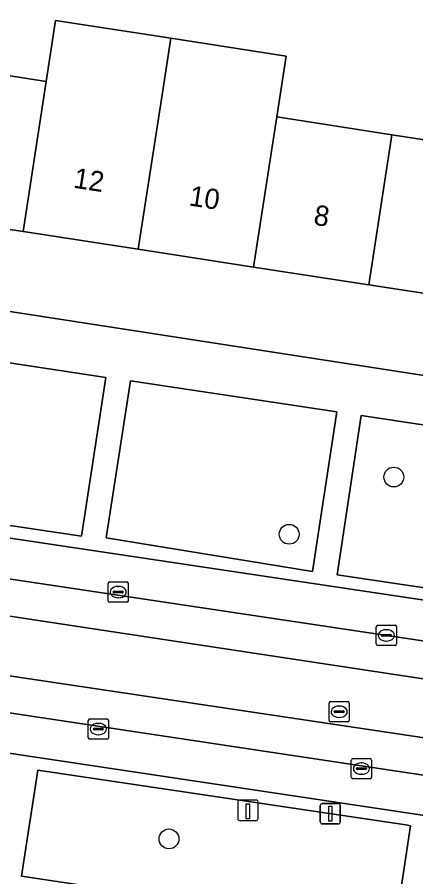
# Model space of a CAD drawing. Extents: x 163008 to 163854, y 382777 to 383982.
# Drawn here: x 163693.29 to 163712.99, y 383182.42 to 383224.9 of the extents above; entities that cross this region are included whole.
import ezdxf

# ---------------------------------------------------------------- set-up
doc = ezdxf.new("R2010")
doc.units = 0
for name, color, linetype in [('IMGEO_Boom', 7, 'Continuous'), ('IMGEO_Erf', 7, 'Continuous'), ('IMGEO_Groenvoorziening', 7, 'Continuous'), ('IMGEO_Kolk', 7, 'Continuous'), ('IMGEO_Laadpaal', 7, 'Continuous'), ('IMGEO_Lichtmast', 7, 'Continuous'), ('IMGEO_Pand', 7, 'Continuous'), ('IMGEO_Pand_nummerreeks', 7, 'Continuous'), ('IMGEO_Parkeervlak_open', 7, 'Continuous'), ('IMGEO_Rijbaan_lokaal_gesloten', 7, 'Continuous'), ('IMGEO_Rijbaan_lokaal_open', 7, 'Continuous'), ('IMGEO_Rioolput', 7, 'Continuous'), ('IMGEO_Voetpad_open', 7, 'Continuous')]:
    doc.layers.add(name, color=color, linetype=linetype)

msp = doc.modelspace()

# ---------------------------------------------------------------- linework, layer by layer
at = {"layer": 'IMGEO_Boom'}
for centre in [(163711.9, 383202.175), (163706.73, 383199.348), (163700.792, 383184.295)]:
    msp.add_circle(centre, 0.489, dxfattribs=at)
at = {"layer": 'IMGEO_Erf'}
for points in [[(163684.611, 383233.617), (163683.271, 383223.496), (163688.213, 383222.734), (163689.034, 383222.607), (163694.727, 383221.729), (163695.191, 383224.738), (163700.883, 383223.86), (163706.576, 383222.981), (163706.112, 383219.973), (163711.805, 383219.095), (163717.497, 383218.217), (163723.191, 383217.338), (163728.883, 383216.46), (163729.422, 383219.714), (163732.229, 383219.226), (163733.2, 383222.188), (163733.748, 383223.859), (163731.488, 383224.563), (163732.505, 383227.826)], [(163732.248, 383205.552), (163732.536, 383208.301), (163727.737, 383209.041), (163722.045, 383209.92), (163716.352, 383210.798), (163710.66, 383211.676), (163704.967, 383212.554), (163699.274, 383213.433), (163693.582, 383214.311), (163687.889, 383215.189), (163682.127, 383216.078), (163681.523, 383212.114), (163730.875, 383204.501)]]:
    msp.add_lwpolyline(points, dxfattribs=at)
at = {"layer": 'IMGEO_Groenvoorziening'}
msp.add_lwpolyline([(163680.772, 383201.601), (163696.473, 383199.252), (163697.671, 383207.096), (163678.06, 383210.077), (163677.488, 383206.169)], dxfattribs=at)
for points in [[(163707.878, 383197.516), (163709.089, 383205.392), (163698.889, 383206.934), (163697.695, 383199.172)], [(163719.297, 383195.827), (163720.527, 383203.663), (163710.287, 383205.219), (163709.093, 383197.343)], [(163712.729, 383184.946), (163712.488, 383184.982), (163710.158, 383185.33), (163694.309, 383187.695), (163693.51, 383182.46), (163711.736, 383179.711), (163711.939, 383179.68)]]:
    msp.add_lwpolyline(points, close=True, dxfattribs=at)
at = {"layer": 'IMGEO_Kolk'}
for p, q in [((163697.857, 383196.991), (163698.709, 383196.991)), ((163697.782, 383196.065), (163697.782, 383196.917)), ((163698.084, 383196.534), (163698.482, 383196.534)), ((163698.27, 383196.771), (163698.295, 383196.771)), ((163698.783, 383196.917), (163698.783, 383196.065)), ((163698.041, 383196.485), (163698.041, 383196.497)), ((163698.479, 383196.448), (163698.081, 383196.448)), ((163698.293, 383196.211), (163698.268, 383196.211)), ((163698.525, 383196.497), (163698.525, 383196.485)), ((163698.709, 383195.991), (163697.857, 383195.991)), ((163711.107, 383194.853), (163711.959, 383194.853)), ((163711.032, 383193.927), (163711.032, 383194.779)), ((163711.334, 383194.396), (163711.732, 383194.396)), ((163711.52, 383194.633), (163711.545, 383194.633)), ((163712.033, 383194.779), (163712.033, 383193.927)), ((163711.291, 383194.347), (163711.291, 383194.359)), ((163711.729, 383194.31), (163711.331, 383194.31)), ((163711.543, 383194.073), (163711.518, 383194.073)), ((163711.775, 383194.359), (163711.775, 383194.347)), ((163711.959, 383193.853), (163711.107, 383193.853)), ((163696.802, 383189.297), (163696.802, 383190.149)), ((163696.877, 383190.223), (163697.729, 383190.223)), ((163697.803, 383190.149), (163697.803, 383189.297)), ((163697.061, 383189.717), (163697.061, 383189.729)), ((163697.104, 383189.766), (163697.502, 383189.766)), ((163697.29, 383190.003), (163697.315, 383190.003)), ((163697.545, 383189.729), (163697.545, 383189.717)), ((163697.499, 383189.68), (163697.101, 383189.68)), ((163697.313, 383189.443), (163697.288, 383189.443)), ((163697.729, 383189.223), (163696.877, 383189.223)), ((163709.8, 383187.341), (163709.8, 383188.193)), ((163709.875, 383188.267), (163710.727, 383188.267)), ((163710.288, 383188.047), (163710.313, 383188.047)), ((163710.801, 383188.193), (163710.801, 383187.341)), ((163710.059, 383187.761), (163710.059, 383187.773)), ((163710.497, 383187.724), (163710.099, 383187.724)), ((163710.102, 383187.81), (163710.5, 383187.81)), ((163710.543, 383187.773), (163710.543, 383187.761)), ((163710.727, 383187.267), (163709.875, 383187.267)), ((163710.311, 383187.487), (163710.286, 383187.487))]:
    msp.add_line(p, q, dxfattribs=at)
for points in [[(163697.857, 383196.991), (163698.709, 383196.991)], [(163697.782, 383196.065), (163697.782, 383196.917)], [(163698.783, 383196.917), (163698.783, 383196.065)], [(163698.709, 383195.991), (163697.857, 383195.991)], [(163711.107, 383194.853), (163711.959, 383194.853)], [(163711.032, 383193.927), (163711.032, 383194.779)], [(163712.033, 383194.779), (163712.033, 383193.927)], [(163711.959, 383193.853), (163711.107, 383193.853)], [(163696.802, 383189.297), (163696.802, 383190.149)], [(163696.877, 383190.223), (163697.729, 383190.223)], [(163697.803, 383190.149), (163697.803, 383189.297)], [(163697.729, 383189.223), (163696.877, 383189.223)], [(163709.8, 383187.341), (163709.8, 383188.193)], [(163709.875, 383188.267), (163710.727, 383188.267)], [(163710.801, 383188.193), (163710.801, 383187.341)], [(163710.727, 383187.267), (163709.875, 383187.267)]]:
    msp.add_lwpolyline(points, dxfattribs=at)
for centre, radius, start, end in [((163697.859, 383196.915), 0.0765, 91.552, 178.448), ((163697.859, 383196.915), 0.0765, 91.552, 178.448), ((163698.707, 383196.915), 0.0765, 1.552, 88.448), ((163698.707, 383196.915), 0.0765, 1.552, 88.448), ((163698.081, 383196.494), 0.0403, 85.8775, 175.7526), ((163698.486, 383196.496), 0.0386, 1.7309, 96.639), ((163698.078, 383196.484), 0.0366, 178.938, 274.7102), ((163698.482, 383196.491), 0.043, 264.8664, 352.4533), ((163697.859, 383196.067), 0.0765, 181.552, 268.448), ((163697.859, 383196.067), 0.0765, 181.552, 268.448), ((163698.707, 383196.067), 0.0765, 271.552, 358.448), ((163698.707, 383196.067), 0.0765, 271.552, 358.448), ((163711.109, 383194.777), 0.0765, 91.552, 178.448), ((163711.109, 383194.777), 0.0765, 91.552, 178.448), ((163711.957, 383194.777), 0.0765, 1.552, 88.448), ((163711.957, 383194.777), 0.0765, 1.552, 88.448), ((163711.331, 383194.356), 0.0403, 85.8775, 175.7526), ((163711.736, 383194.358), 0.0386, 1.7309, 96.639), ((163711.328, 383194.346), 0.0366, 178.938, 274.7102), ((163711.732, 383194.353), 0.043, 264.8664, 352.4533), ((163711.109, 383193.929), 0.0765, 181.552, 268.448), ((163711.109, 383193.929), 0.0765, 181.552, 268.448), ((163711.957, 383193.929), 0.0765, 271.552, 358.448), ((163711.957, 383193.929), 0.0765, 271.552, 358.448), ((163696.879, 383190.147), 0.0765, 91.552, 178.448), ((163696.879, 383190.147), 0.0765, 91.552, 178.448), ((163697.727, 383190.147), 0.0765, 1.552, 88.448), ((163697.727, 383190.147), 0.0765, 1.552, 88.448), ((163697.101, 383189.726), 0.0403, 85.8775, 175.7526), ((163697.506, 383189.728), 0.0386, 1.7309, 96.639), ((163696.879, 383189.299), 0.0765, 181.552, 268.448), ((163696.879, 383189.299), 0.0765, 181.552, 268.448), ((163697.098, 383189.716), 0.0366, 178.938, 274.7102), ((163697.502, 383189.723), 0.043, 264.8664, 352.4533), ((163697.727, 383189.299), 0.0765, 271.552, 358.448), ((163697.727, 383189.299), 0.0765, 271.552, 358.448), ((163709.877, 383188.191), 0.0765, 91.552, 178.448), ((163709.877, 383188.191), 0.0765, 91.552, 178.448), ((163710.725, 383188.191), 0.0765, 1.552, 88.448), ((163710.725, 383188.191), 0.0765, 1.552, 88.448), ((163710.099, 383187.77), 0.0403, 85.8775, 175.7526), ((163710.096, 383187.76), 0.0366, 178.938, 274.7102), ((163710.5, 383187.767), 0.043, 264.8664, 352.4533), ((163710.504, 383187.772), 0.0386, 1.7309, 96.639), ((163709.877, 383187.343), 0.0765, 181.552, 268.448), ((163709.877, 383187.343), 0.0765, 181.552, 268.448), ((163710.725, 383187.343), 0.0765, 271.552, 358.448), ((163710.725, 383187.343), 0.0765, 271.552, 358.448)]:
    msp.add_arc(centre, radius, start, end, dxfattribs=at)
for centre, major_axis, ratio, start_param, end_param in [((163698.269, 383196.491), (-0.387, 0.002), 0.722429, 4.712389, 7.853982), ((163698.294, 383196.491), (-0.39, 0.002), 0.717154, 1.570796, 4.712389), ((163711.519, 383194.353), (-0.387, 0.002), 0.722429, 4.712389, 7.853982), ((163711.544, 383194.353), (-0.39, 0.002), 0.717154, 1.570796, 4.712389), ((163697.289, 383189.723), (-0.387, 0.002), 0.722429, 4.712389, 7.853982), ((163697.314, 383189.723), (-0.39, 0.002), 0.717154, 1.570796, 4.712389), ((163710.287, 383187.767), (-0.387, 0.002), 0.722429, 4.712389, 7.853982), ((163710.312, 383187.767), (-0.39, 0.002), 0.717154, 1.570796, 4.712389)]:
    msp.add_ellipse(centre, major_axis=major_axis, ratio=ratio, start_param=start_param, end_param=end_param, dxfattribs=at)
at = {"layer": 'IMGEO_Laadpaal'}
for p, q in [((163704.19, 383186.125), (163704.19, 383185.284)), ((163704.19, 383186.125), (163704.19, 383185.284)), ((163705.106, 383186.209), (163704.265, 383186.209)), ((163705.106, 383186.209), (163704.265, 383186.209)), ((163705.19, 383185.293), (163705.19, 383186.134)), ((163705.19, 383185.293), (163705.19, 383186.134)), ((163704.274, 383185.209), (163705.115, 383185.209)), ((163704.274, 383185.209), (163705.115, 383185.209))]:
    msp.add_line(p, q, dxfattribs=at)
msp.add_lwpolyline([(163704.605, 383186.022), (163704.765, 383186.022), (163704.765, 383185.289), (163704.605, 383185.289), (163704.605, 383186.022)], dxfattribs=at)
for centre, start, end in [((163704.268, 383186.131), 92.4484, 184.2845), ((163704.268, 383186.131), 92.4484, 184.2845), ((163705.112, 383186.131), 2.4484, 94.2845), ((163705.112, 383186.131), 2.4484, 94.2845), ((163704.268, 383185.287), 182.4484, 274.2845), ((163704.268, 383185.287), 182.4484, 274.2845), ((163705.112, 383185.287), 272.4484, 4.2845), ((163705.112, 383185.287), 272.4484, 4.2845)]:
    msp.add_arc(centre, 0.0779, start, end, dxfattribs=at)
at = {"layer": 'IMGEO_Lichtmast'}
for p, q in [((163708.264, 383185.139), (163708.264, 383185.939)), ((163708.264, 383185.939), (163708.264, 383185.139)), ((163708.364, 383186.039), (163709.154, 383186.039)), ((163709.154, 383186.039), (163708.364, 383186.039)), ((163709.254, 383185.939), (163709.254, 383185.139)), ((163709.254, 383185.139), (163709.254, 383185.939)), ((163709.154, 383185.039), (163708.364, 383185.039)), ((163708.364, 383185.039), (163709.154, 383185.039))]:
    msp.add_line(p, q, dxfattribs=at)
msp.add_lwpolyline([(163708.684, 383185.914), (163708.834, 383185.914), (163708.834, 383185.164), (163708.684, 383185.164), (163708.684, 383185.914)], dxfattribs=at)
for centre, start, end in [((163708.364, 383185.939), 90, 180), ((163708.364, 383185.939), 90, 180), ((163709.154, 383185.939), 0, 90), ((163709.154, 383185.939), 360, 90), ((163708.364, 383185.139), 180, 270), ((163708.364, 383185.139), 180, 270), ((163709.154, 383185.139), 270, 0), ((163709.154, 383185.139), 270, 0)]:
    msp.add_arc(centre, 0.1, start, end, dxfattribs=at)
at = {"layer": 'IMGEO_Pand'}
for points in [[(163700.883, 383223.86), (163695.191, 383224.738), (163694.727, 383221.729), (163693.582, 383214.311), (163699.274, 383213.433), (163700.419, 383220.851)], [(163700.883, 383223.86), (163700.419, 383220.851), (163699.274, 383213.433), (163704.967, 383212.554), (163706.112, 383219.973), (163706.576, 383222.981)], [(163689.034, 383222.607), (163687.889, 383215.189), (163693.582, 383214.311), (163694.727, 383221.729)], [(163704.967, 383212.554), (163710.66, 383211.676), (163711.805, 383219.095), (163706.112, 383219.973)], [(163716.352, 383210.798), (163717.497, 383218.217), (163711.805, 383219.095), (163710.66, 383211.676)]]:
    msp.add_lwpolyline(points, close=True, dxfattribs=at)
at = {"layer": 'IMGEO_Parkeervlak_open'}
for points in [[(163729.304, 383193.723), (163728.371, 383193.855), (163683.358, 383200.592)], [(163680.106, 383199.055), (163681.322, 383198.871), (163732.344, 383191.24)], [(163731.089, 383184.778), (163680.418, 383192.402), (163679.168, 383192.59)], [(163682.217, 383190.134), (163727.793, 383183.29)]]:
    msp.add_lwpolyline(points, dxfattribs=at)
at = {"layer": 'IMGEO_Rijbaan_lokaal_gesloten'}
for points in [[(163681.073, 383197.092), (163734.101, 383189.06), (163734.379, 383190.942), (163732.344, 383191.24), (163681.322, 383198.871)], [(163680.667, 383194.179), (163680.418, 383192.402), (163731.089, 383184.778), (163733.408, 383184.421), (163733.682, 383186.255)]]:
    msp.add_lwpolyline(points, close=True, dxfattribs=at)
at = {"layer": 'IMGEO_Rijbaan_lokaal_open'}
msp.add_lwpolyline([(163733.682, 383186.255), (163734.101, 383189.06), (163681.073, 383197.092), (163680.667, 383194.179)], close=True, dxfattribs=at)
at = {"layer": 'IMGEO_Rioolput'}
for p, q in [((163708.699, 383190.151), (163708.699, 383191.003)), ((163708.774, 383191.077), (163709.626, 383191.077)), ((163709.7, 383191.003), (163709.7, 383190.151)), ((163708.958, 383190.571), (163708.958, 383190.583)), ((163709.001, 383190.62), (163709.399, 383190.62)), ((163709.187, 383190.857), (163709.212, 383190.857)), ((163709.442, 383190.583), (163709.442, 383190.571)), ((163709.396, 383190.534), (163708.998, 383190.534)), ((163709.21, 383190.297), (163709.185, 383190.297)), ((163709.626, 383190.077), (163708.774, 383190.077))]:
    msp.add_line(p, q, dxfattribs=at)
for points in [[(163708.699, 383190.151), (163708.699, 383191.003)], [(163708.774, 383191.077), (163709.626, 383191.077)], [(163709.7, 383191.003), (163709.7, 383190.151)], [(163709.626, 383190.077), (163708.774, 383190.077)]]:
    msp.add_lwpolyline(points, dxfattribs=at)
for centre, radius, start, end in [((163708.776, 383191.001), 0.0765, 91.552, 178.448), ((163708.776, 383191.001), 0.0765, 91.552, 178.448), ((163709.624, 383191.001), 0.0765, 1.552, 88.448), ((163709.624, 383191.001), 0.0765, 1.552, 88.448), ((163708.998, 383190.58), 0.0403, 85.8775, 175.7526), ((163708.995, 383190.57), 0.0366, 178.938, 274.7102), ((163709.399, 383190.577), 0.043, 264.8664, 352.4533), ((163709.403, 383190.582), 0.0386, 1.7309, 96.639), ((163708.776, 383190.153), 0.0765, 181.552, 268.448), ((163708.776, 383190.153), 0.0765, 181.552, 268.448), ((163709.624, 383190.153), 0.0765, 271.552, 358.448), ((163709.624, 383190.153), 0.0765, 271.552, 358.448)]:
    msp.add_arc(centre, radius, start, end, dxfattribs=at)
for centre, major_axis, ratio, start_param, end_param in [((163709.186, 383190.577), (-0.387, 0.002), 0.722429, 4.712389, 7.853982), ((163709.211, 383190.577), (-0.39, 0.002), 0.717154, 1.570796, 4.712389)]:
    msp.add_ellipse(centre, major_axis=major_axis, ratio=ratio, start_param=start_param, end_param=end_param, dxfattribs=at)
at = {"layer": 'IMGEO_Voetpad_open'}
for points in [[(163730.875, 383204.501), (163681.523, 383212.114), (163675.78, 383213.262), (163675.609, 383210.462), (163675.478, 383209.634), (163674.891, 383205.8)], [(163677.488, 383206.169), (163678.06, 383210.077), (163697.671, 383207.096), (163696.473, 383199.252), (163680.772, 383201.601)], [(163683.358, 383200.592), (163728.371, 383193.855), (163729.304, 383193.723)], [(163727.793, 383183.29), (163682.217, 383190.134)]]:
    msp.add_lwpolyline(points, dxfattribs=at)
for points in [[(163707.878, 383197.516), (163697.695, 383199.172), (163698.889, 383206.934), (163709.089, 383205.392)], [(163719.297, 383195.827), (163709.093, 383197.343), (163710.287, 383205.219), (163720.527, 383203.663)], [(163711.939, 383179.68), (163711.736, 383179.711), (163693.51, 383182.46), (163694.309, 383187.695), (163710.158, 383185.33), (163712.488, 383184.982), (163712.729, 383184.946)]]:
    msp.add_lwpolyline(points, close=True, dxfattribs=at)

# ---------------------------------------------------------------- texts
at = {"layer": 'IMGEO_Pand_nummerreeks'}
for s, p in [('12', (163696.034, 383216.482)), ('10', (163701.742, 383215.603)), ('8', (163707.899, 383214.652))]:
    msp.add_text(s, height=1, rotation=351.2297, dxfattribs=at).set_placement(p)

doc.saveas('drawing.dxf')
